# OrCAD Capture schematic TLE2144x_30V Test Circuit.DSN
size A; title: TLE214x, TLE214xA EXCALIBUR LOW-NOISE HIGH-SPEED; rev: 1.0; note: Datasheet: SLOS183D EVM: N/A
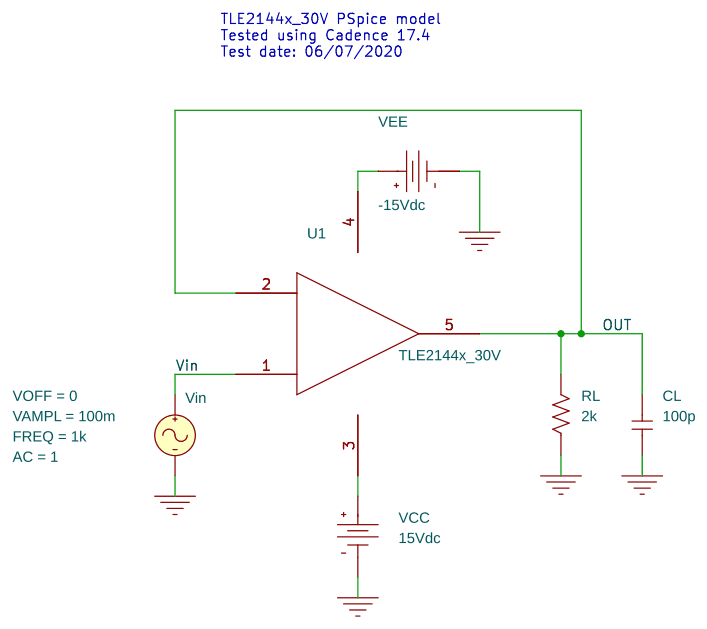
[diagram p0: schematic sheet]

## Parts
CL  100p  [RAD/CK05]
RL  2k  [AX/RC05]
U1  TLE2144x_30V
VCC  VDC
VEE  VDC
Vin  VSIN

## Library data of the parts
CL = C
RL = R
U1 = TLE2144x_30V
VCC = VDC: DC: 15Vdc
VEE = VDC: DC: -15Vdc
Vin = VSIN: AC: 1; FREQ: 1k; VAMPL: 100m; VOFF: 0

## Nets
Vin: U1.1(IN+) Vin.1(+)
0: CL.1 RL.1 VCC.1(-) VEE.1(-) Vin.2(-)
OUT: CL.2 RL.2 U1.2(IN-) U1.5(OUT)
N22995: U1.4(VEE) VEE.0(+)
N23017: U1.3(VCC) VCC.0(+)

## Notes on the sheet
- TLE2144x_30V PSpice model
  Tested using Cadence 17.4
  Test date: 06/07/2020
